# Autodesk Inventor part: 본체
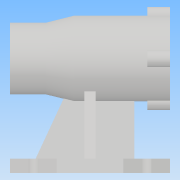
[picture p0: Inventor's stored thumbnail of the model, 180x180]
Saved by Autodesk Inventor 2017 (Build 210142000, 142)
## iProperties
Part Number: 본체
Material: 일반
Document SubType Name: Modeling
Designer: user
Density: 1 g/cm^3
Appearance: 기본값
Author: user
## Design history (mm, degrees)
sketch "스케치1"
  geometry: L1 (-56, 0)-(56, 0); L2 (-56, 0)-(-56, 25); L3 (-56, 25)-(-31, 25); L4 (-31, 25)-(-11, 30); L5 (-11, 30)-(56, 30); L6 (56, 30)-(56, 0); 2 further points
  constraints: 12 end point, 2 perpendicular, 1 coincident, 1 horizontal, 1 midpoint, 1 parallel, 1 vertical
  dimensions: "d0" = 112 distance of L1.start L1.end; "d1" = 25 distance of L2.end L3.end; "d2" = 45 distance from line of L4.end L2; "d3" = 50 diameter of L3 L1; "d4" = 60 diameter of L5 L1
revolve "회전1" sketch "스케치1" stored, may be unused: angle "d5" = 90 deg
sketch "스케치2"
  geometry: L1 (56, -30)-(56, 30) reference; L2 (-50, 0)-(56, 0); L3 (56, 0)-(56, 21); L4 (56, 21)-(41, 21); L5 (41, 21)-(41, 21); L6 (38, 24)-(-10, 24); L7 (-13, 21)-(-13, 21); L8 (-13, 21)-(-24.7, 21); L9 (-25, 20.7)-(-25, 17.5); L10 (-25, 17.5)-(-42.7, 17.5); L11 (-43, 17.2)-(-43, 16); L12 (-43, 16)-(-46.7, 16); L13 (-47, 15.7)-(-47, 10.5); L14 (-47, 10.5)-(-47, 10.5); L15 (-50, 7.5)-(-50, 0); A1 r 0.3 centre (-46.7, 15.7) between (-46.7, 16) and (-47, 15.7); A2 r 0.3 centre (-42.7, 17.2) between (-42.7, 17.5) and (-43, 17.2); A3 r 0.3 centre (-24.7, 20.7) between (-24.7, 21) and (-25, 20.7); A4 r 3 centre (-47, 7.5) between (-47, 10.5) and (-50, 7.5); A5 r 3 centre (-10, 21) between (-10, 24) and (-13, 21); A6 r 3 centre (38, 21) between (41, 21) and (38, 24); 7 further points
  constraints: 28 end point, 15 point on line, 12 point on circle, 12 tangent, 9 perpendicular, 6 centre point, 4 equal radius, 1 horizontal, 1 midpoint, 1 vertical
  dimensions: "d6" = 42 diameter of L4 L2; "d7" = 48 diameter of L6 L2; "d8" = 35 diameter of L10 L2; "d9" = 32 diameter of L12 L2; "d10" = 21 diameter of L14 L2; "d11" = 3 distance of L13.end point (-50, 10.5); "d12" = 4 distance of L11.end point (-47, 16); "d13" = 18 distance of L9.end point (-43, 17.5); "d14" = 54 distance of point (41, 24) point (-13, 24); "d15" = 15 distance of L3.end L4.end; "d16" = 12 distance of L7.end point (-25, 21); "d17" = 0.3 radius of A1; "d18" = 3 radius of A4
revolve "회전2" sketch "스케치2" stored, may be unused: angle "d19" = 90 deg
chamfer "모따기1" distance "d20" = 1; stored, may be unused: second distance "d21" = 2, angle "d22" = 45 deg
node "작업 평면1"
sketch "스케치3"
  geometry: L1 (-56, 30)-(-56, -30) reference; L2 (-23.196, -56.48)-(-56, -23.676); L3 (-56, -23.676)-(-56, 22.716); L4 (-56, 22.716)-(-23.196, 55.52); L5 (-23.196, 55.52)-(23.196, 55.52); L6 (23.196, 55.52)-(56, 22.716); L7 (56, 22.716)-(56, -23.676); L8 (56, -23.676)-(23.196, -56.48); L9 (23.196, -56.48)-(-23.196, -56.48); C1 r 56 at (0, -0.48); 2 further points
  constraints: 16 end point, 1 centre point, 1 coincident, 1 collinear, 1 tangent, 17 other
  dimensions: "d24" = 112 diameter of C1
extrude "돌출1" join sketch "스케치3" distance "d25" = 10; taper "d26" = 0 deg
sketch "스케치4"
  geometry: L1 (-56, 23.676)-(-56, -22.716) reference; L2 (56, -22.716)-(56, 23.676) reference; L3 (-38, -4)-(31, -4); L4 (31, -4)-(31, 4); L5 (31, 4)-(-38, 4); L6 (-38, 4)-(-38, -4); L7 (-38, -4)-(31, 4); L8 (31, -4)-(-38, 4); 3 further points
  constraints: 12 end point, 3 midpoint, 2 parallel, 1 horizontal, 1 horizontal alignment, 1 perpendicular
  dimensions: "d27" = 8 distance of L3.end L4.end; "d28" = 25 distance between parallel lines of L2 L4; "d29" = 18 distance between parallel lines of L1 L6
extrude "돌출2" join sketch "스케치4" stored distance "d30" = 10; taper "d31" = 0 deg
feature "면 기울기1" dims angle "d32" = 25 deg
sketch "스케치5"
  geometry: L1 (-70, -56.48)-(-80, -56.48) reference; L2 (-80, -56.48)-(-80, 55.52) reference; L3 (-80, 55.52)-(-70, 55.52) reference; L4 (-70, 55.52)-(-70, 4) reference; L5 (-70, 4)-(-29.732, 4) reference; L6 (-29.732, -4)-(-70, -4) reference; L7 (-70, -4)-(-70, -56.48) reference; L8 (-70, -36.48)-(-22.928, -19.347); C1 r 24 at (0, 0) reference; A1 r 30 centre (0, 0) between (-29.732, -4) and (-29.732, 4) reference; 1 further point
  constraints: 2 end point, 1 point on circle, 1 point on line
  dimensions: "d33" = 20 distance of L1.start L8.start; "d34" = 110 deg angle of L7 L8
feature "리브1" sketch "스케치5" dims "d35" = 1, "d36" = 8, "d37" = 0, "d38" = 0, "d39" = 1, "d40" = 1
sketch "스케치6"
  geometry: C1 r 6 at (0, 30); 1 further point
  constraints: 2 vertical alignment, 1 centre point, 1 other
  dimensions: "d41" = 12 diameter of C1
extrude "돌출3" join sketch "스케치6" distance "d42" = 16; taper "d43" = 0 deg
hole "구멍1" diameter "d49" = 3.242; stored, may be unused: countersink angle "d53" = 90 deg, drill point angle "d55" = 118 deg; dims "d47" = 10, "d48" = 10, "d50" = 8, "d51" = 4, "d52" = 2, "d54" = 11
sketch "스케치7"
  geometry: L1 (-56, 23.676)-(-56, -22.716) reference; L2 (56, -22.716)-(56, 23.676) reference; L3 (0, 0)-(-56, 0); L4 (0, 0)-(56, 0); C1 r 5 at (-39.598, 39.598); C2 r 5 at (39.598, 39.598); A1 r 56 centre (0, 0) between (-39.598, 39.598) and (-56, 0); 1 further point
  constraints: 4 end point, 4 point on circle, 3 centre point, 2 point on line, 1 coincident
  dimensions: "d59" = 112 diameter of A1; "d60" = 10 diameter of C1; "d61" = 45 deg dimension on point (0, 0) L3.end C1.centre; "d62" = 10 diameter of C2; "d63" = 45 deg dimension on point (0, 0) L4.end C2.centre
extrude "돌출4" cut sketch "스케치7" stored distance "d64" = 16; taper "d65" = 0 deg
node "솔리드1"
mirror "미러1"
pattern_circular "원형 패턴1" dims angle "d45" = 360 deg
pattern_circular "원형 패턴2" dims angle "d57" = 360 deg
mirror "미러2"
node "절단 모서리 투영1"
